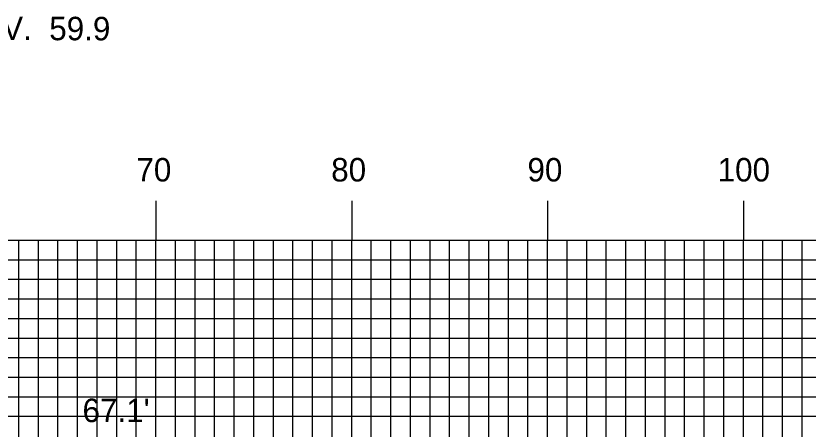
# Model space of a CAD drawing. Extents: x 1774777 to 1775120, y 442591 to 442811.
# Drawn here: x 1775005.53 to 1775045.99, y 442664.01 to 442685.13 of the extents above; entities that cross this region are included whole.
import ezdxf

# ---------------------------------------------------------------- set-up
doc = ezdxf.new("R2010")
doc.units = 0
for name, color, linetype in [('BORING - REFUSAL', 7, 'Continuous'), ('D_Text_Standard', 7, 'Continuous'), ('H_V ANNOTATION', 7, 'Continuous'), ('MAJOR', 7, 'Continuous'), ('MINOR', 7, 'Continuous')]:
    doc.layers.add(name, color=color, linetype=linetype)

msp = doc.modelspace()

# ---------------------------------------------------------------- linework, layer by layer
at = {"layer": 'MAJOR'}
for p, q in [((1775012.685, 442675.669), (1775012.685, 442673.665)), ((1775022.685, 442675.669), (1775022.685, 442673.665)), ((1775032.685, 442675.669), (1775032.685, 442673.665)), ((1775042.685, 442675.669), (1775042.685, 442673.665)), ((1774802.685, 442673.665), (1775082.685, 442673.665)), ((1774802.685, 442673.665), (1775082.685, 442673.665)), ((1775012.685, 442648.665), (1775012.685, 442673.665)), ((1775022.685, 442648.665), (1775022.685, 442673.665)), ((1775032.685, 442648.665), (1775032.685, 442673.665)), ((1775042.685, 442648.665), (1775042.685, 442673.665)), ((1774802.685, 442668.665), (1775082.685, 442668.665))]:
    msp.add_line(p, q, dxfattribs=at)
at = {"layer": 'MINOR'}
for p, q in [((1775005.685, 442648.665), (1775005.685, 442673.665)), ((1775006.685, 442648.665), (1775006.685, 442673.665)), ((1775007.685, 442648.665), (1775007.685, 442673.665)), ((1775008.685, 442648.665), (1775008.685, 442673.665)), ((1775009.685, 442648.665), (1775009.685, 442673.665)), ((1775010.685, 442648.665), (1775010.685, 442673.665)), ((1775011.685, 442648.665), (1775011.685, 442673.665)), ((1775013.685, 442648.665), (1775013.685, 442673.665)), ((1775014.685, 442648.665), (1775014.685, 442673.665)), ((1775015.685, 442648.665), (1775015.685, 442673.665)), ((1775016.685, 442648.665), (1775016.685, 442673.665)), ((1775017.685, 442648.665), (1775017.685, 442673.665)), ((1775018.685, 442648.665), (1775018.685, 442673.665)), ((1775019.685, 442648.665), (1775019.685, 442673.665)), ((1775020.685, 442648.665), (1775020.685, 442673.665)), ((1775021.685, 442648.665), (1775021.685, 442673.665)), ((1775023.685, 442648.665), (1775023.685, 442673.665)), ((1775024.685, 442648.665), (1775024.685, 442673.665)), ((1775025.685, 442648.665), (1775025.685, 442673.665)), ((1775026.685, 442648.665), (1775026.685, 442673.665)), ((1775027.685, 442648.665), (1775027.685, 442673.665)), ((1775028.685, 442648.665), (1775028.685, 442673.665)), ((1775029.685, 442648.665), (1775029.685, 442673.665)), ((1775030.685, 442648.665), (1775030.685, 442673.665)), ((1775031.685, 442648.665), (1775031.685, 442673.665)), ((1775033.685, 442648.665), (1775033.685, 442673.665)), ((1775034.685, 442648.665), (1775034.685, 442673.665)), ((1775035.685, 442648.665), (1775035.685, 442673.665)), ((1775036.685, 442648.665), (1775036.685, 442673.665)), ((1775037.685, 442648.665), (1775037.685, 442673.665)), ((1775038.685, 442648.665), (1775038.685, 442673.665)), ((1775039.685, 442648.665), (1775039.685, 442673.665)), ((1775040.685, 442648.665), (1775040.685, 442673.665)), ((1775041.685, 442648.665), (1775041.685, 442673.665)), ((1775043.685, 442648.665), (1775043.685, 442673.665)), ((1775044.685, 442648.665), (1775044.685, 442673.665)), ((1775045.685, 442648.665), (1775045.685, 442673.665)), ((1774802.685, 442672.665), (1775082.685, 442672.665)), ((1774802.685, 442671.665), (1775082.685, 442671.665)), ((1774802.685, 442670.665), (1775082.685, 442670.665)), ((1774802.685, 442669.665), (1775082.685, 442669.665)), ((1774802.685, 442667.665), (1775082.685, 442667.665)), ((1774802.685, 442666.665), (1775082.685, 442666.665)), ((1774802.685, 442665.665), (1775082.685, 442665.665)), ((1774802.685, 442664.665), (1775082.685, 442664.665))]:
    msp.add_line(p, q, dxfattribs=at)

# ---------------------------------------------------------------- texts
at = {"layer": 'BORING - REFUSAL'}
msp.add_text('APPROX. ELEV.  59.9', height=1.2, rotation=359.8142, dxfattribs=at).set_placement((1774994.216, 442683.927))
at = {"layer": 'D_Text_Standard'}
msp.add_text("67.1'", height=1.2, dxfattribs=at).set_placement((1775008.937, 442664.368))
at = {"layer": 'H_V ANNOTATION'}
for s, p in [('70', (1775011.689, 442676.665)), ('80', (1775021.636, 442676.665)), ('90', (1775031.657, 442676.665)), ('100', (1775041.369, 442676.665))]:
    msp.add_text(s, height=1.2, dxfattribs=at).set_placement(p)

doc.saveas('drawing.dxf')
